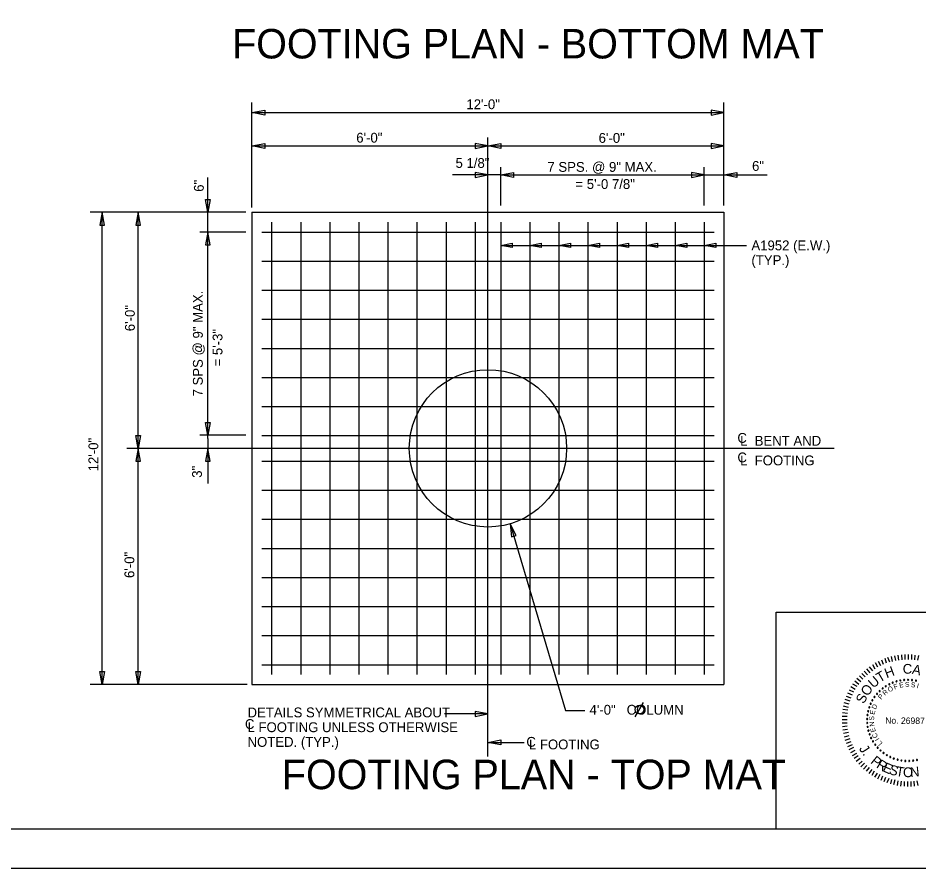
# Model space of a CAD drawing. Extents: x 1970675.2 to 1970711.3, y 796145.2 to 796167.2.
# Drawn here: x 1970688.23 to 1970699.69, y 796145.25 to 796156.05 of the extents above; entities that cross this region are included whole.
import ezdxf

# ---------------------------------------------------------------- set-up
doc = ezdxf.new("R2010")
doc.units = 0
for name, color, linetype in [('BR_AUTO DIMENSION', 7, 'Continuous'), ('BR_BORDER LINES', 7, 'Continuous'), ('BR_CENTER LINES', 7, 'Continuous'), ('BR_CONCRETE', 7, 'Continuous'), ('BR_REBAR', 7, 'Continuous'), ('BR_TEXT', 7, 'Continuous'), ('Level 31', 7, 'Continuous')]:
    doc.layers.add(name, color=color, linetype=linetype)

msp = doc.modelspace()

# ---------------------------------------------------------------- linework, layer by layer
at = {"layer": 'BR_AUTO DIMENSION'}
for p, q in [((1970691.208, 796153.64), (1970691.208, 796154.976)), ((1970697.208, 796153.665), (1970697.208, 796154.976)), ((1970691.208, 796154.848), (1970697.208, 796154.848)), ((1970691.208, 796154.424), (1970694.208, 796154.424)), ((1970694.208, 796154.424), (1970697.208, 796154.424)), ((1970694.37, 796153.665), (1970694.37, 796154.152)), ((1970696.958, 796153.665), (1970696.958, 796154.152)), ((1970690.648, 796153.094), (1970690.648, 796154.023)), ((1970694.37, 796154.055), (1970693.757, 796154.055)), ((1970694.37, 796154.055), (1970697.757, 796154.055)), ((1970691.13, 796153.58), (1970689.151, 796153.58)), ((1970689.304, 796147.58), (1970689.304, 796153.58)), ((1970689.762, 796150.58), (1970689.762, 796153.58)), ((1970691.13, 796153.33), (1970690.547, 796153.33)), ((1970690.648, 796150.705), (1970690.648, 796153.33)), ((1970694.37, 796153.159), (1970697.496, 796153.159)), ((1970691.13, 796150.747), (1970690.547, 796150.747)), ((1970690.648, 796150.705), (1970690.648, 796150.132)), ((1970689.762, 796147.58), (1970689.762, 796150.58)), ((1970694.492, 796149.621), (1970695.195, 796147.246)), ((1970691.148, 796147.58), (1970689.151, 796147.58)), ((1970695.195, 796147.246), (1970695.439, 796147.246)), ((1970694.208, 796147.204), (1970693.656, 796147.204)), ((1970694.208, 796146.842), (1970694.669, 796146.842))]:
    msp.add_line(p, q, dxfattribs=at)
for points in [[(1970691.37, 796154.816), (1970691.208, 796154.848), (1970691.37, 796154.879)], [(1970697.045, 796154.816), (1970697.208, 796154.848), (1970697.045, 796154.879)], [(1970691.37, 796154.393), (1970691.208, 796154.424), (1970691.37, 796154.455)], [(1970694.045, 796154.393), (1970694.208, 796154.424), (1970694.045, 796154.455)], [(1970694.37, 796154.393), (1970694.208, 796154.424), (1970694.37, 796154.455)], [(1970697.045, 796154.393), (1970697.208, 796154.424), (1970697.045, 796154.455)], [(1970694.045, 796154.023), (1970694.208, 796154.055), (1970694.045, 796154.086)], [(1970694.532, 796154.023), (1970694.37, 796154.055), (1970694.532, 796154.086)], [(1970696.795, 796154.023), (1970696.958, 796154.055), (1970696.795, 796154.086)], [(1970697.37, 796154.023), (1970697.208, 796154.055), (1970697.37, 796154.086)], [(1970690.679, 796153.743), (1970690.648, 796153.58), (1970690.616, 796153.743)], [(1970689.335, 796153.418), (1970689.304, 796153.58), (1970689.273, 796153.418)], [(1970689.793, 796153.418), (1970689.762, 796153.58), (1970689.731, 796153.418)], [(1970690.679, 796153.168), (1970690.648, 796153.33), (1970690.616, 796153.168)], [(1970694.516, 796153.131), (1970694.37, 796153.159), (1970694.516, 796153.187)], [(1970694.886, 796153.131), (1970694.74, 796153.159), (1970694.886, 796153.187)], [(1970695.256, 796153.131), (1970695.109, 796153.159), (1970695.256, 796153.187)], [(1970695.625, 796153.131), (1970695.479, 796153.159), (1970695.625, 796153.187)], [(1970695.995, 796153.131), (1970695.849, 796153.159), (1970695.995, 796153.187)], [(1970696.365, 796153.131), (1970696.218, 796153.159), (1970696.365, 796153.187)], [(1970696.734, 796153.131), (1970696.588, 796153.159), (1970696.734, 796153.187)], [(1970697.104, 796153.131), (1970696.958, 796153.159), (1970697.104, 796153.187)], [(1970690.679, 796150.909), (1970690.648, 796150.747), (1970690.616, 796150.909)], [(1970689.793, 796150.743), (1970689.762, 796150.58), (1970689.731, 796150.743)], [(1970689.793, 796150.418), (1970689.762, 796150.58), (1970689.731, 796150.418)], [(1970690.679, 796150.418), (1970690.648, 796150.58), (1970690.616, 796150.418)], [(1970694.568, 796149.474), (1970694.492, 796149.621), (1970694.508, 796149.457)], [(1970689.335, 796147.743), (1970689.304, 796147.58), (1970689.273, 796147.743)], [(1970689.793, 796147.743), (1970689.762, 796147.58), (1970689.731, 796147.743)], [(1970694.045, 796147.172), (1970694.208, 796147.204), (1970694.045, 796147.235)], [(1970694.37, 796146.811), (1970694.208, 796146.842), (1970694.37, 796146.874)]]:
    msp.add_lwpolyline(points, close=True, dxfattribs=at)
at = {"layer": 'BR_BORDER LINES'}
for p, q in [((1970697.87, 796148.496), (1970703.236, 796148.496)), ((1970697.87, 796145.746), (1970697.87, 796148.496)), ((1970677.07, 796145.746), (1970710.736, 796145.746))]:
    msp.add_line(p, q, dxfattribs=at)
at = {"layer": 'BR_CENTER LINES'}
for p, q in [((1970694.208, 796146.664), (1970694.208, 796154.53)), ((1970698.608, 796150.58), (1970689.616, 796150.58))]:
    msp.add_line(p, q, dxfattribs=at)
at = {"layer": 'BR_CONCRETE'}
for p, q in [((1970691.208, 796153.58), (1970697.208, 796153.58)), ((1970691.208, 796153.58), (1970691.208, 796147.58)), ((1970697.208, 796153.58), (1970697.208, 796147.58)), ((1970691.208, 796147.58), (1970697.208, 796147.58))]:
    msp.add_line(p, q, dxfattribs=at)
msp.add_circle((1970694.208, 796150.58), 1, dxfattribs=at)
at = {"layer": 'BR_REBAR'}
for p, q in [((1970691.458, 796153.455), (1970691.458, 796147.705)), ((1970691.828, 796153.455), (1970691.828, 796147.705)), ((1970692.197, 796153.455), (1970692.197, 796147.705)), ((1970692.567, 796153.455), (1970692.567, 796147.705)), ((1970692.937, 796153.455), (1970692.937, 796147.705)), ((1970693.306, 796153.455), (1970693.306, 796147.705)), ((1970693.676, 796153.455), (1970693.676, 796147.705)), ((1970694.046, 796153.455), (1970694.046, 796147.705)), ((1970694.37, 796153.455), (1970694.37, 796147.705)), ((1970694.37, 796153.455), (1970694.37, 796147.705)), ((1970694.74, 796153.455), (1970694.74, 796147.705)), ((1970695.109, 796153.455), (1970695.109, 796147.705)), ((1970695.479, 796153.455), (1970695.479, 796147.705)), ((1970695.849, 796153.455), (1970695.849, 796147.705)), ((1970696.218, 796153.455), (1970696.218, 796147.705)), ((1970696.588, 796153.455), (1970696.588, 796147.705)), ((1970696.958, 796153.455), (1970696.958, 796147.705)), ((1970691.333, 796153.33), (1970697.083, 796153.33)), ((1970691.333, 796152.96), (1970697.083, 796152.96)), ((1970691.333, 796152.591), (1970697.083, 796152.591)), ((1970691.333, 796152.221), (1970697.083, 796152.221)), ((1970691.333, 796151.851), (1970697.083, 796151.851)), ((1970691.333, 796151.482), (1970697.083, 796151.482)), ((1970691.333, 796151.112), (1970697.083, 796151.112)), ((1970691.333, 796150.742), (1970697.083, 796150.742)), ((1970691.333, 796150.742), (1970697.083, 796150.742)), ((1970691.333, 796150.418), (1970697.083, 796150.418)), ((1970691.333, 796150.048), (1970697.083, 796150.048)), ((1970691.333, 796149.679), (1970697.083, 796149.679)), ((1970691.333, 796149.309), (1970697.083, 796149.309)), ((1970691.333, 796148.939), (1970697.083, 796148.939)), ((1970691.333, 796148.569), (1970697.083, 796148.569)), ((1970691.333, 796148.2), (1970697.083, 796148.2)), ((1970691.333, 796147.83), (1970697.083, 796147.83))]:
    msp.add_line(p, q, dxfattribs=at)
at = {"layer": 'BR_TEXT'}
for p, q in [((1970699.351, 796147.872), (1970699.338, 796147.933)), ((1970699.392, 796147.882), (1970699.378, 796147.941)), ((1970699.432, 796147.889), (1970699.423, 796147.95)), ((1970699.472, 796147.893), (1970699.468, 796147.954)), ((1970699.511, 796147.896), (1970699.512, 796147.96)), ((1970699.553, 796147.898), (1970699.554, 796147.96)), ((1970699.595, 796147.895), (1970699.597, 796147.959)), ((1970699.635, 796147.892), (1970699.64, 796147.953)), ((1970699.674, 796147.887), (1970699.685, 796147.948)), ((1970699.13, 796147.774), (1970699.099, 796147.829)), ((1970699.165, 796147.798), (1970699.135, 796147.852)), ((1970699.2, 796147.816), (1970699.174, 796147.872)), ((1970699.237, 796147.833), (1970699.213, 796147.889)), ((1970699.275, 796147.85), (1970699.255, 796147.908)), ((1970699.315, 796147.862), (1970699.293, 796147.92)), ((1970699.003, 796147.676), (1970698.959, 796147.72)), ((1970699.032, 796147.703), (1970698.991, 796147.748)), ((1970699.065, 796147.728), (1970699.025, 796147.778)), ((1970699.099, 796147.753), (1970699.06, 796147.804)), ((1970698.901, 796147.551), (1970698.847, 796147.584)), ((1970698.922, 796147.58), (1970698.873, 796147.62)), ((1970698.948, 796147.614), (1970698.899, 796147.653)), ((1970698.973, 796147.645), (1970698.93, 796147.688)), ((1970698.859, 796147.481), (1970698.802, 796147.508)), ((1970698.876, 796147.515), (1970698.822, 796147.547)), ((1970698.812, 796147.365), (1970698.75, 796147.388)), ((1970698.824, 796147.405), (1970698.766, 796147.427)), ((1970698.841, 796147.444), (1970698.784, 796147.469)), ((1970696.08, 796147.168), (1970696.185, 796147.35)), ((1970698.781, 796147.251), (1970698.721, 796147.259)), ((1970698.792, 796147.287), (1970698.729, 796147.303)), ((1970698.799, 796147.329), (1970698.738, 796147.344)), ((1970698.774, 796147.171), (1970698.709, 796147.171)), ((1970698.772, 796147.129), (1970698.709, 796147.13)), ((1970698.777, 796147.21), (1970698.715, 796147.217)), ((1970698.773, 796147.086), (1970698.709, 796147.085)), ((1970698.775, 796147.048), (1970698.714, 796147.041)), ((1970698.779, 796147.007), (1970698.718, 796146.998)), ((1970698.789, 796146.967), (1970698.727, 796146.954)), ((1970698.796, 796146.925), (1970698.735, 796146.911)), ((1970698.808, 796146.888), (1970698.746, 796146.867)), ((1970698.819, 796146.849), (1970698.761, 796146.828)), ((1970698.836, 796146.812), (1970698.778, 796146.785)), ((1970698.853, 796146.776), (1970698.796, 796146.746)), ((1970698.87, 796146.739), (1970698.816, 796146.708)), ((1970698.894, 796146.702), (1970698.839, 796146.671)), ((1970698.915, 796146.673), (1970698.865, 796146.636)), ((1970698.94, 796146.639), (1970698.89, 796146.6)), ((1970698.965, 796146.605), (1970698.921, 796146.564)), ((1970698.994, 796146.579), (1970698.949, 796146.534)), ((1970699.023, 796146.549), (1970698.98, 796146.503)), ((1970699.055, 796146.523), (1970699.014, 796146.476)), ((1970699.088, 796146.497), (1970699.049, 796146.449)), ((1970699.119, 796146.475), (1970699.088, 796146.423)), ((1970699.154, 796146.453), (1970699.123, 796146.399)), ((1970699.188, 796146.433), (1970699.161, 796146.377)), ((1970699.225, 796146.415), (1970699.201, 796146.36)), ((1970699.263, 796146.398), (1970699.242, 796146.341)), ((1970699.303, 796146.385), (1970699.28, 796146.327)), ((1970699.339, 796146.373), (1970699.325, 796146.314)), ((1970699.38, 796146.366), (1970699.365, 796146.304)), ((1970699.419, 796146.354), (1970699.409, 796146.296)), ((1970699.459, 796146.35), (1970699.454, 796146.288)), ((1970699.498, 796146.347), (1970699.498, 796146.285)), ((1970699.54, 796146.344), (1970699.54, 796146.283)), ((1970699.582, 796146.346), (1970699.584, 796146.284)), ((1970699.623, 796146.348), (1970699.626, 796146.286)), ((1970699.661, 796146.352), (1970699.671, 796146.294))]:
    msp.add_line(p, q, dxfattribs=at)
msp.add_circle((1970696.133, 796147.259), 0.055, dxfattribs=at)
for centre, start, end in [((1970699.309, 796147.581), 27.2191, 207.2191), ((1970699.309, 796147.581), 207.2191, 27.2191), ((1970699.354, 796147.602), 21.6807, 201.6807), ((1970699.354, 796147.602), 201.6807, 21.6807), ((1970699.401, 796147.618), 16.1422, 196.1422), ((1970699.401, 796147.618), 196.1422, 16.1422), ((1970699.45, 796147.629), 10.6038, 190.6038), ((1970699.45, 796147.629), 190.6038, 10.6038), ((1970699.499, 796147.636), 5.0653, 185.0653), ((1970699.499, 796147.636), 185.0653, 5.0653), ((1970699.549, 796147.638), 359.5268, 179.5268), ((1970699.549, 796147.638), 179.5268, 359.5268), ((1970699.599, 796147.635), 353.9884, 173.9884), ((1970699.599, 796147.635), 173.9884, 353.9884), ((1970699.648, 796147.627), 348.4499, 168.4499), ((1970699.648, 796147.627), 168.4499, 348.4499), ((1970699.187, 796147.495), 43.8345, 223.8345), ((1970699.187, 796147.495), 223.8345, 43.8345), ((1970699.225, 796147.528), 38.2961, 218.2961), ((1970699.225, 796147.528), 218.2961, 38.2961), ((1970699.265, 796147.557), 32.7576, 212.7576), ((1970699.265, 796147.557), 212.7576, 32.7576), ((1970699.095, 796147.378), 60.4499, 240.4499), ((1970699.095, 796147.378), 240.4499, 60.4499), ((1970699.122, 796147.42), 54.9114, 234.9114), ((1970699.122, 796147.42), 234.9114, 54.9114), ((1970699.153, 796147.459), 49.373, 229.373), ((1970699.153, 796147.459), 229.373, 49.373), ((1970699.041, 796147.239), 77.0653, 257.0653), ((1970699.041, 796147.239), 257.0653, 77.0653), ((1970699.055, 796147.287), 71.5268, 251.5268), ((1970699.055, 796147.287), 251.5268, 71.5268), ((1970699.073, 796147.333), 65.9884, 245.9884), ((1970699.073, 796147.333), 245.9884, 65.9884), ((1970699.028, 796147.14), 88.1422, 268.1422), ((1970699.032, 796147.19), 82.6038, 262.6038), ((1970699.028, 796147.14), 268.1422, 88.1422), ((1970699.032, 796147.19), 262.6038, 82.6038), ((1970699.029, 796147.09), 93.6807, 273.6807), ((1970699.034, 796147.041), 99.2191, 279.2191), ((1970699.029, 796147.09), 273.6807, 93.6807), ((1970699.034, 796147.041), 279.2191, 99.2191), ((1970699.045, 796146.992), 104.7576, 284.7576), ((1970699.045, 796146.992), 284.7576, 104.7576), ((1970699.059, 796146.944), 110.2961, 290.2961), ((1970699.059, 796146.944), 290.2961, 110.2961), ((1970699.079, 796146.898), 115.8345, 295.8345), ((1970699.079, 796146.898), 295.8345, 115.8345), ((1970699.103, 796146.855), 121.373, 301.373), ((1970699.103, 796146.855), 301.373, 121.373), ((1970699.131, 796146.813), 126.9114, 306.9114), ((1970699.131, 796146.813), 306.9114, 126.9114), ((1970699.162, 796146.775), 132.4499, 312.4499), ((1970699.162, 796146.775), 312.4499, 132.4499), ((1970699.198, 796146.74), 137.9884, 317.9884), ((1970699.198, 796146.74), 317.9884, 137.9884), ((1970699.236, 796146.708), 143.5268, 323.5268), ((1970699.236, 796146.708), 323.5268, 143.5268), ((1970699.278, 796146.68), 149.0653, 329.0653), ((1970699.278, 796146.68), 329.0653, 149.0653), ((1970699.321, 796146.657), 154.6038, 334.6038), ((1970699.321, 796146.657), 334.6038, 154.6038), ((1970699.367, 796146.638), 160.1422, 340.1422), ((1970699.367, 796146.638), 340.1422, 160.1422), ((1970699.415, 796146.623), 345.6807, 165.6807), ((1970699.415, 796146.623), 165.6807, 345.6807), ((1970699.464, 796146.613), 351.2191, 171.2191), ((1970699.464, 796146.613), 171.2191, 351.2191), ((1970699.513, 796146.607), 356.7576, 176.7576), ((1970699.513, 796146.607), 176.7576, 356.7576), ((1970699.563, 796146.607), 2.2961, 182.2961), ((1970699.563, 796146.607), 182.2961, 2.2961), ((1970699.613, 796146.611), 7.8345, 187.8345), ((1970699.613, 796146.611), 187.8345, 7.8345), ((1970699.662, 796146.62), 13.373, 193.373), ((1970699.662, 796146.62), 193.373, 13.373)]:
    msp.add_arc(centre, 0.00701, start, end, dxfattribs=at)
at = {"layer": 'Level 31'}
msp.add_lwpolyline([(1970675.236, 796145.246), (1970711.236, 796145.246), (1970711.236, 796167.246), (1970675.236, 796167.246)], close=True, dxfattribs=at)

# ---------------------------------------------------------------- texts
at = {"layer": 'BR_AUTO DIMENSION'}
for s, p in [('12\'-0"', (1970693.934, 796154.891)), ('6\'-0"', (1970692.534, 796154.466)), ('6\'-0"', (1970695.615, 796154.463)), ('C', (1970697.379, 796150.65)), ('C', (1970697.379, 796150.402)), ('C', (1970691.119, 796147.013)), ('C', (1970694.696, 796146.787))]:
    msp.add_text(s, height=0.125, dxfattribs=at).set_placement(p)
for s, p in [('6\'-0"', (1970689.719, 796152.069)), ('12\'-0"', (1970689.255, 796150.288)), ('6\'-0"', (1970689.713, 796148.932))]:
    msp.add_text(s, height=0.125, rotation=90, dxfattribs=at).set_placement(p)
at = {"layer": 'BR_TEXT'}
for s, height, p in [('FOOTING PLAN - BOTTOM MAT', 0.375, (1970690.956, 796155.536)), ('7 SPS. @ 9" MAX.', 0.125, (1970694.964, 796154.095)), ('6"', 0.125, (1970697.565, 796154.107)), ('= 5\'-0 7/8"', 0.125, (1970695.32, 796153.877)), ('A1952 (E.W.)', 0.125, (1970697.557, 796153.097)), ('(TYP.)', 0.125, (1970697.557, 796152.91)), ('L  BENT AND', 0.125, (1970697.413, 796150.614)), ('L  FOOTING', 0.125, (1970697.413, 796150.364)), ('DETAILS SYMMETRICAL ABOUT ', 0.125, (1970691.152, 796147.161)), ('4\'-0"   COLUMN', 0.125, (1970695.499, 796147.195)), ('L FOOTING UNLESS OTHERWISE', 0.125, (1970691.152, 796146.973)), ('NOTED. (TYP.)', 0.125, (1970691.152, 796146.786)), ('L FOOTING', 0.125, (1970694.729, 796146.754)), ('FOOTING PLAN - TOP MAT', 0.375, (1970691.589, 796146.248))]:
    msp.add_text(s, height=height, dxfattribs=at).set_placement(p)
for s, height, rotation, p in [('5 1/8"', 0.125, 360, (1970693.796, 796154.145)), ('6"', 0.125, 90, (1970690.596, 796153.841)), ('7 SPS @ 9" MAX.', 0.125, 90, (1970690.583, 796151.24)), ('= 5\'-3"', 0.125, 90, (1970690.833, 796151.621)), ('3"', 0.125, 90, (1970690.572, 796150.206)), ('C', 0.124, 359.5482, (1970699.48, 796147.716)), ('A', 0.124, 348.1981, (1970699.592, 796147.716)), ('T', 0.124, 30.4992, (1970699.188, 796147.6)), ('H', 0.124, 20.3637, (1970699.276, 796147.657)), ('U', 0.124, 40.8022, (1970699.107, 796147.525)), ('F', 0.0622, 20.6127, (1970699.377, 796147.514)), ('E', 0.0622, 11.4103, (1970699.442, 796147.536)), ('S', 0.0622, 2.208, (1970699.51, 796147.547)), ('S', 0.0622, 352.6608, (1970699.581, 796147.547)), ('I', 0.0622, 343.1136, (1970699.652, 796147.535)), ('O', 0.124, 52.0267, (1970699.032, 796147.421)), ('R', 0.0622, 40.3949, (1970699.254, 796147.434)), ('O', 0.0622, 30.8477, (1970699.31, 796147.478)), ('S', 0.124, 63.2511, (1970698.987, 796147.325)), ('P', 0.0622, 49.9421, (1970699.206, 796147.382)), ('E', 0.0622, 78.2388, (1970699.122, 796147.19)), ('D', 0.0622, 69.0364, (1970699.139, 796147.257)), ('S', 0.0622, 87.786, (1970699.116, 796147.119)), ('No. 26987', 0.0817, 359.5268, (1970699.257, 796147.08)), ('N', 0.0622, 97.3332, (1970699.122, 796147.048)), ('E', 0.0622, 106.5355, (1970699.14, 796146.981)), ('C', 0.0622, 116.4266, (1970699.169, 796146.914)), ('I', 0.0622, 121.1011, (1970699.187, 796146.884)), ('J', 0.124, 302.9559, (1970698.92, 796146.763)), ('L', 0.0622, 129.9595, (1970699.228, 796146.832)), ('.', 0.124, 309.3974, (1970698.964, 796146.695)), ('P', 0.124, 321.1035, (1970699.063, 796146.586)), ('R', 0.124, 328.5359, (1970699.136, 796146.528)), ('E', 0.124, 335.9684, (1970699.216, 796146.48)), ('S', 0.124, 343.0292, (1970699.297, 796146.444)), ('T', 0.124, 350.4617, (1970699.387, 796146.418)), ('O', 0.124, 358.1419, (1970699.482, 796146.403)), ('N', 0.124, 5.8221, (1970699.579, 796146.401))]:
    msp.add_text(s, height=height, rotation=rotation, dxfattribs=at).set_placement(p)

doc.saveas('drawing.dxf')
